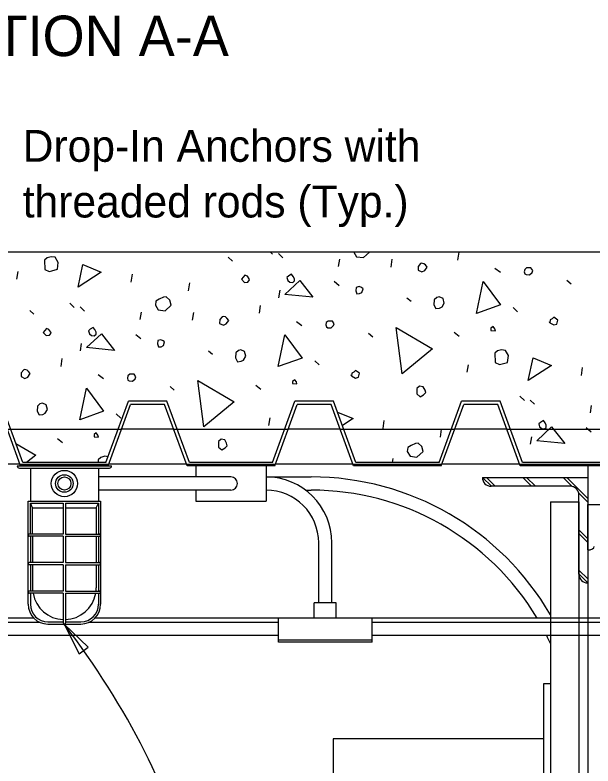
# Model space of a CAD drawing. Extents: x 112544 to 112597.1, y 111084 to 111107.1.
# Drawn here: x 112559.102 to 112561.845, y 111092 to 111095.563 of the extents above; entities that cross this region are included whole.
import ezdxf

# ---------------------------------------------------------------- set-up
doc = ezdxf.new("R2010")
doc.units = 0
for name, color, linetype in [('Dimension', 7, 'Continuous'), ('Lighting', 7, 'Continuous'), ('Lighting_h', 7, 'Continuous'), ('Miscellaneous', 7, 'Continuous'), ('SteelGirder', 7, 'Continuous'), ('SteelGirder_h', 7, 'Continuous'), ('SupstrConc', 7, 'Continuous'), ('TextStructures', 7, 'Continuous')]:
    doc.layers.add(name, color=color, linetype=linetype)

msp = doc.modelspace()

# ---------------------------------------------------------------- linework, layer by layer
at = {"layer": 'Dimension'}
msp.add_lwpolyline([(112559.3342, 111092.6735), (112559.4058, 111092.5322), (112559.4483, 111092.5637)], close=True, dxfattribs=at)
msp.add_ellipse((112558.9681, 111092.2177), major_axis=(-0.8636, 1.2185), ratio=0.378675, start_param=2.874358, end_param=4.819841, dxfattribs=at)
at = {"layer": 'Lighting'}
for p, q in [((112559.112, 111093.4235), (112559.5599, 111093.4235)), ((112559.1224, 111093.4131), (112559.5495, 111093.4131)), ((112559.1745, 111093.4235), (112559.4974, 111093.4235)), ((112559.1745, 111093.4131), (112559.1745, 111093.2568)), ((112559.4974, 111093.4131), (112559.4974, 111093.2568)), ((112560.2931, 111093.4235), (112559.9598, 111093.4235)), ((112559.9598, 111093.4235), (112559.9598, 111093.3714)), ((112560.2931, 111093.4235), (112560.2931, 111093.2568)), ((112560.1264, 111093.3714), (112559.4974, 111093.3714)), ((112560.2931, 111093.3714), (112560.5076, 111093.3714)), ((112560.1264, 111093.3089), (112559.4974, 111093.3089)), ((112559.9598, 111093.3089), (112559.9598, 111093.2568)), ((112560.4806, 111093.3089), (112560.5076, 111093.3089)), ((112559.1641, 111092.7672), (112559.1641, 111093.2568)), ((112559.1641, 111093.2568), (112559.1745, 111093.2568)), ((112559.1745, 111093.2568), (112559.4974, 111093.2568)), ((112559.1745, 111093.1006), (112559.1745, 111093.2464)), ((112559.1745, 111093.2464), (112559.3308, 111093.2464)), ((112559.1849, 111093.2256), (112559.1745, 111093.2464)), ((112559.3308, 111093.2464), (112559.3308, 111093.1006)), ((112559.3412, 111093.2464), (112559.4974, 111093.2464)), ((112559.3412, 111093.2464), (112559.3412, 111093.1006)), ((112559.487, 111093.2256), (112559.4974, 111093.2464)), ((112559.4974, 111093.2568), (112559.5078, 111093.2568)), ((112559.4974, 111093.2464), (112559.4974, 111093.1006)), ((112559.5078, 111093.2568), (112559.5078, 111092.7672)), ((112559.9598, 111093.2568), (112560.2931, 111093.2568)), ((112561.6431, 111093.254), (112561.6431, 111092.3909)), ((112561.6431, 111093.254), (112561.7785, 111093.254)), ((112561.7785, 111093.254), (112561.7785, 111088.8165)), ((112559.1849, 111093.2256), (112559.3308, 111093.2256)), ((112559.3412, 111093.2256), (112559.487, 111093.2256)), ((112559.3308, 111093.1006), (112559.1693, 111093.1006)), ((112559.3308, 111093.0902), (112559.1693, 111093.0902)), ((112559.1745, 111093.0902), (112559.1745, 111092.9652)), ((112559.3308, 111093.0902), (112559.3308, 111092.9652)), ((112559.3412, 111093.1006), (112559.5026, 111093.1006)), ((112559.3412, 111093.0902), (112559.5026, 111093.0902)), ((112559.3412, 111093.0902), (112559.3412, 111092.9652)), ((112559.4974, 111093.0902), (112559.4974, 111092.9652)), ((112560.5431, 111092.774), (112560.5431, 111093.0589)), ((112560.6056, 111092.774), (112560.6056, 111093.0589)), ((112559.3308, 111092.9652), (112559.1693, 111092.9652)), ((112559.3412, 111092.9652), (112559.5026, 111092.9652)), ((112559.3308, 111092.9548), (112559.1693, 111092.9548)), ((112559.1745, 111092.9548), (112559.1745, 111092.8298)), ((112559.3308, 111092.9548), (112559.3308, 111092.8298)), ((112559.3412, 111092.9548), (112559.5026, 111092.9548)), ((112559.3412, 111092.9548), (112559.3412, 111092.8298)), ((112559.4974, 111092.9548), (112559.4974, 111092.8298)), ((112559.3308, 111092.8298), (112559.1693, 111092.8298)), ((112559.3308, 111092.8194), (112559.1693, 111092.8194)), ((112559.1745, 111092.8194), (112559.1745, 111092.7672)), ((112559.3308, 111092.8194), (112559.3308, 111092.6787)), ((112559.3412, 111092.8298), (112559.5026, 111092.8298)), ((112559.3412, 111092.8194), (112559.5026, 111092.8194)), ((112559.3412, 111092.8194), (112559.3412, 111092.6787)), ((112559.4974, 111092.8194), (112559.4974, 111092.7672)), ((112560.6264, 111092.774), (112560.5223, 111092.774)), ((112560.5223, 111092.7018), (112560.5223, 111092.774)), ((112560.6264, 111092.7018), (112560.6264, 111092.774)), ((112559.1907, 111092.7018), (112558.4355, 111092.7018)), ((112559.2211, 111092.681), (112558.4355, 111092.681)), ((112559.2578, 111092.6839), (112559.3308, 111092.6839)), ((112559.3412, 111092.6839), (112559.4141, 111092.6839)), ((112560.3522, 111092.681), (112559.4509, 111092.681)), ((112560.3805, 111092.7018), (112559.4813, 111092.7018)), ((112560.3522, 111092.5877), (112560.3522, 111092.7018)), ((112561.6431, 111092.7018), (112560.3522, 111092.7018)), ((112560.7964, 111092.5877), (112560.7964, 111092.7018)), ((112561.6431, 111092.681), (112560.7964, 111092.681)), ((112559.2578, 111092.6735), (112559.4141, 111092.6735)), ((112560.3522, 111092.6185), (112558.4355, 111092.6185)), ((112561.6431, 111092.6185), (112560.7964, 111092.6185)), ((112560.7964, 111092.5977), (112560.3522, 111092.5977)), ((112560.7964, 111092.5877), (112560.3522, 111092.5877))]:
    msp.add_line(p, q, dxfattribs=at)
msp.add_lwpolyline([(112561.6119, 111089.4034), (112561.6119, 111092.1284), (112560.6119, 111092.1284), (112560.6119, 111089.4034), (112561.5494, 111089.4034)], dxfattribs=at)
for radius in [0.0625, 0.0417, 0.0312]:
    msp.add_circle((112559.336, 111093.3402), radius, dxfattribs=at)
for centre, radius, start, end in [((112559.1224, 111093.4235), 0.0104, 180, 270), ((112559.5495, 111093.4235), 0.0104, 270, 0), ((112560.1264, 111093.3402), 0.0312, 270, 90), ((112560.2931, 111093.0589), 0.3125, 0, 90), ((112560.5076, 111092.0589), 1.3125, 30.1068, 90), ((112560.2931, 111093.0589), 0.25, 0, 90), ((112560.5076, 111092.0589), 1.25, 30.9531, 90), ((112559.1693, 111093.0954), 0.0052, 89.9999, 270), ((112559.5026, 111093.0954), 0.0052, 270, 90.0001), ((112559.1693, 111092.96), 0.0052, 89.9999, 270), ((112559.5026, 111092.96), 0.0052, 270, 90.0001), ((112559.1693, 111092.8246), 0.0052, 89.9999, 270), ((112559.5026, 111092.8246), 0.0052, 270, 90.0001), ((112559.2578, 111092.7672), 0.0937, 180, 270), ((112559.2578, 111092.7672), 0.0833, 180, 270), ((112559.4141, 111092.7672), 0.0833, 270, 0), ((112559.4141, 111092.7672), 0.0937, 270, 0), ((112559.336, 111092.6787), 0.0052, 179.9665, 0), ((112560.5076, 111092.0589), 1.25, 24.7221, 26.596)]:
    msp.add_arc(centre, radius, start, end, dxfattribs=at)
at = {"layer": 'Lighting_h'}
for p, q in [((112562.2368, 111092.7018), (112561.6431, 111092.7018)), ((112562.2368, 111092.681), (112561.6431, 111092.681)), ((112562.2368, 111092.6185), (112561.6431, 111092.6185))]:
    msp.add_line(p, q, dxfattribs=at)
at = {"layer": 'Miscellaneous'}
for p, q in [((112560.3127, 111094.4392), (112560.324, 111094.4283)), ((112560.3518, 111094.4306), (112560.3728, 111094.4103)), ((112561.2038, 111094.4), (112561.2092, 111094.4377)), ((112560.1132, 111094.4132), (112560.1335, 111094.3954)), ((112560.6373, 111094.3699), (112560.6434, 111094.4052)), ((112560.8866, 111094.3668), (112560.892, 111094.4045)), ((112561.3797, 111094.3618), (112561.4055, 111094.3428)), ((112559.1107, 111094.3102), (112559.1168, 111094.3455)), ((112559.6531, 111094.2951), (112559.6585, 111094.3328)), ((112559.9255, 111094.2542), (112559.9309, 111094.2919)), ((112560.6172, 111094.2998), (112560.6406, 111094.2802)), ((112561.7208, 111094.3056), (112561.7411, 111094.2878)), ((112560.3535, 111094.2214), (112560.3596, 111094.2567)), ((112560.9618, 111094.2213), (112560.9815, 111094.2059)), ((112559.3612, 111094.1962), (112559.3822, 111094.1759)), ((112559.4101, 111094.1782), (112559.431, 111094.158)), ((112560.262, 111094.1477), (112560.2674, 111094.1854)), ((112561.4659, 111094.1752), (112561.4869, 111094.155)), ((112559.1714, 111094.1609), (112559.1917, 111094.143)), ((112559.6955, 111094.1175), (112559.7016, 111094.1528)), ((112559.9448, 111094.1145), (112559.9502, 111094.1521)), ((112560.4379, 111094.1094), (112560.4637, 111094.0904)), ((112559.6755, 111094.0475), (112559.6988, 111094.0278)), ((112560.779, 111094.0533), (112560.7994, 111094.0354)), ((112561.1865, 111094.0589), (112561.2098, 111094.0393)), ((112559.4118, 111093.969), (112559.4178, 111094.0043)), ((112560.02, 111093.969), (112560.0397, 111093.9535)), ((112559.3202, 111093.8953), (112559.3256, 111093.933)), ((112560.5241, 111093.9229), (112560.5451, 111093.9026)), ((112561.2479, 111093.8683), (112561.254, 111093.9036)), ((112561.7903, 111093.8532), (112561.7957, 111093.8909)), ((112559.4961, 111093.8571), (112559.5219, 111093.8381)), ((112559.8373, 111093.8009), (112559.8576, 111093.7831)), ((112560.2447, 111093.8066), (112560.2681, 111093.787)), ((112561.4984, 111093.7543), (112561.5194, 111093.734)), ((112559.1277, 111093.4235), (112559.0215, 111093.7153)), ((112559.1386, 111093.4391), (112559.0324, 111093.7309)), ((112559.5334, 111093.4391), (112559.6396, 111093.7309)), ((112559.5443, 111093.4235), (112559.6505, 111093.7153)), ((112559.8229, 111093.7309), (112559.6396, 111093.7309)), ((112559.8119, 111093.7153), (112559.6505, 111093.7153)), ((112559.9181, 111093.4235), (112559.8119, 111093.7153)), ((112559.9291, 111093.4391), (112559.8229, 111093.7309)), ((112560.3238, 111093.4391), (112560.43, 111093.7309)), ((112560.3347, 111093.4235), (112560.4409, 111093.7153)), ((112560.6133, 111093.7309), (112560.43, 111093.7309)), ((112560.6024, 111093.7153), (112560.4409, 111093.7153)), ((112560.7086, 111093.4235), (112560.6024, 111093.7153)), ((112560.7195, 111093.4391), (112560.6133, 111093.7309)), ((112561.1142, 111093.4391), (112561.2204, 111093.7309)), ((112561.1252, 111093.4235), (112561.2314, 111093.7153)), ((112561.4037, 111093.7309), (112561.2204, 111093.7309)), ((112561.3928, 111093.7153), (112561.2314, 111093.7153)), ((112561.499, 111093.4235), (112561.3928, 111093.7153)), ((112561.5099, 111093.4391), (112561.4037, 111093.7309)), ((112561.5473, 111093.7363), (112561.5682, 111093.7161)), ((112561.8327, 111093.6756), (112561.8388, 111093.7109)), ((112559.5823, 111093.6705), (112559.6033, 111093.6503)), ((112560.3061, 111093.616), (112560.3122, 111093.6513)), ((112560.8485, 111093.6009), (112560.8539, 111093.6385)), ((112561.8126, 111093.6056), (112561.836, 111093.5859)), ((112561.1209, 111093.56), (112561.1263, 111093.5976)), ((112559.3029, 111093.5542), (112559.3263, 111093.5346)), ((112561.549, 111093.5271), (112561.555, 111093.5624)), ((112559.5334, 111093.4391), (112559.1386, 111093.4391)), ((112560.3238, 111093.4391), (112559.9291, 111093.4391)), ((112561.1142, 111093.4391), (112560.7195, 111093.4391)), ((112560.8936, 111093.4391), (112560.897, 111093.4586)), ((112561.9047, 111093.4391), (112561.5099, 111093.4391)), ((112559.5443, 111093.4235), (112559.1277, 111093.4235)), ((112560.3347, 111093.4235), (112559.9181, 111093.4235)), ((112561.1252, 111093.4235), (112560.7086, 111093.4235)), ((112561.9156, 111093.4235), (112561.499, 111093.4235)), ((112561.363, 111093.3269), (112561.3214, 111093.3686)), ((112561.3807, 111093.3269), (112561.339, 111093.3686)), ((112561.554, 111093.3269), (112561.5123, 111093.3686)), ((112561.5716, 111093.3269), (112561.53, 111093.3686)), ((112561.7473, 111093.3245), (112561.7032, 111093.3686)), ((112561.8201, 111093.2693), (112561.7209, 111093.3686)), ((112561.8201, 111093.2517), (112561.7758, 111093.296)), ((112559.1849, 111093.1006), (112559.1849, 111093.2256)), ((112559.487, 111093.2256), (112559.487, 111093.1006)), ((112561.8201, 111093.0784), (112561.7785, 111093.1201)), ((112559.1849, 111093.0902), (112559.1849, 111092.9652)), ((112559.487, 111093.0902), (112559.487, 111092.9652)), ((112561.8201, 111093.0607), (112561.7785, 111093.1024)), ((112559.1849, 111092.9548), (112559.1849, 111092.8453)), ((112559.487, 111092.9548), (112559.487, 111092.8453)), ((112561.8201, 111092.8875), (112561.7785, 111092.9292)), ((112561.8201, 111092.8698), (112561.7785, 111092.9115))]:
    msp.add_line(p, q, dxfattribs=at)
for points in [[(112560.7095, 111094.4384), (112560.7232, 111094.4162), (112560.7554, 111094.4119), (112560.7847, 111094.4379), (112560.7843, 111094.4392)], [(112560.7096, 111094.4392), (112560.7095, 111094.4384)], [(112559.242, 111094.3998), (112559.2433, 111094.3561), (112559.2641, 111094.3462), (112559.2762, 111094.3494), (112559.3028, 111094.3565), (112559.3071, 111094.3887), (112559.2927, 111094.4134), (112559.2739, 111094.4161), (112559.2545, 111094.4109), (112559.242, 111094.3998)], [(112559.4006, 111094.2715), (112559.4237, 111094.3786), (112559.511, 111094.3425), (112559.4006, 111094.2715)], [(112561.0151, 111094.3702), (112561.0148, 111094.352), (112561.0325, 111094.3438), (112561.0463, 111094.3501), (112561.0576, 111094.366), (112561.0495, 111094.3768), (112561.0428, 111094.3828), (112561.0318, 111094.385), (112561.027, 111094.3837), (112561.0151, 111094.3702)], [(112561.5214, 111094.335), (112561.5275, 111094.3315), (112561.5433, 111094.3306), (112561.5559, 111094.3417), (112561.5588, 111094.3502), (112561.5501, 111094.3634), (112561.5294, 111094.3631), (112561.5211, 111094.3556), (112561.5188, 111094.3447), (112561.5214, 111094.335)], [(112560.1774, 111094.3088), (112560.1916, 111094.2945), (112560.2067, 111094.2959), (112560.2145, 111094.3058), (112560.2132, 111094.3106), (112560.2045, 111094.3238), (112560.1929, 111094.3285), (112560.1851, 111094.3186), (112560.1774, 111094.3088)], [(112560.3964, 111094.3028), (112560.4063, 111094.2951), (112560.4196, 111094.2935), (112560.428, 111094.3009), (112560.4278, 111094.3112), (112560.4222, 111094.3226), (112560.4141, 111094.3334), (112560.4009, 111094.3247), (112560.3926, 111094.3173), (112560.3964, 111094.3028)], [(112560.383, 111094.237), (112560.4534, 111094.3025), (112560.516, 111094.2235), (112560.383, 111094.237)], [(112561.2923, 111094.1468), (112561.3244, 111094.2978), (112561.4057, 111094.1875), (112561.2923, 111094.1468)], [(112560.7199, 111094.2548), (112560.7237, 111094.2404), (112560.7365, 111094.2412), (112560.7479, 111094.2468), (112560.7537, 111094.2639), (112560.7469, 111094.2699), (112560.7353, 111094.2745), (112560.7208, 111094.2706), (112560.7199, 111094.2548)], [(112559.7677, 111094.1861), (112559.7814, 111094.1639), (112559.8136, 111094.1596), (112559.8429, 111094.1855), (112559.8365, 111094.2097), (112559.8192, 111094.2257), (112559.8065, 111094.2249), (112559.786, 111094.2143), (112559.7704, 111094.2049), (112559.7677, 111094.1861)], [(112561.0911, 111094.212), (112561.0897, 111094.1883), (112561.0997, 111094.1703), (112561.1172, 111094.1724), (112561.1287, 111094.178), (112561.1393, 111094.1964), (112561.1335, 111094.2181), (112561.1157, 111094.2263), (112561.1037, 111094.2231), (112561.0911, 111094.212)], [(112560.0733, 111094.1178), (112560.073, 111094.0996), (112560.0907, 111094.0914), (112560.1046, 111094.0977), (112560.1158, 111094.1137), (112560.1077, 111094.1245), (112560.101, 111094.1304), (112560.09, 111094.1327), (112560.0852, 111094.1314), (112560.0733, 111094.1178)], [(112560.5796, 111094.0827), (112560.5858, 111094.0792), (112560.6016, 111094.0782), (112560.6141, 111094.0893), (112560.617, 111094.0979), (112560.6083, 111094.1111), (112560.5877, 111094.1107), (112560.5793, 111094.1033), (112560.5771, 111094.0923), (112560.5796, 111094.0827)], [(112561.6405, 111094.103), (112561.6589, 111094.0924), (112561.6734, 111094.0962), (112561.6785, 111094.1157), (112561.6595, 111094.1287), (112561.6512, 111094.1213), (112561.6421, 111094.1163), (112561.6405, 111094.103), (112561.6393, 111094.1078)], [(112559.2356, 111094.0564), (112559.2498, 111094.0421), (112559.265, 111094.0436), (112559.2727, 111094.0534), (112559.2714, 111094.0583), (112559.2627, 111094.0714), (112559.2511, 111094.0761), (112559.2434, 111094.0663), (112559.2356, 111094.0564)], [(112559.4547, 111094.0504), (112559.4645, 111094.0427), (112559.4779, 111094.0411), (112559.4862, 111094.0485), (112559.4861, 111094.0588), (112559.4804, 111094.0703), (112559.4723, 111094.081), (112559.4591, 111094.0723), (112559.4508, 111094.0649), (112559.4547, 111094.0504)], [(112560.9394, 111093.8607), (112560.9114, 111094.081), (112561.0835, 111093.9796), (112560.9394, 111093.8607)], [(112561.3604, 111094.0667), (112561.3816, 111094.0646), (112561.3791, 111094.0743), (112561.371, 111094.0851), (112561.3602, 111094.077), (112561.3604, 111094.0667)], [(112559.4412, 111093.9847), (112559.5117, 111094.0502), (112559.5742, 111093.9712), (112559.4412, 111093.9847)], [(112560.3506, 111093.8945), (112560.3826, 111094.0454), (112560.4639, 111093.9352), (112560.3506, 111093.8945)], [(112559.7781, 111094.0025), (112559.782, 111093.988), (112559.7947, 111093.9888), (112559.8061, 111093.9945), (112559.8119, 111094.0116), (112559.8051, 111094.0175), (112559.7935, 111094.0222), (112559.779, 111094.0183), (112559.7781, 111094.0025)], [(112560.1493, 111093.9596), (112560.1479, 111093.9359), (112560.1579, 111093.9179), (112560.1755, 111093.92), (112560.1869, 111093.9257), (112560.1975, 111093.9441), (112560.1917, 111093.9658), (112560.174, 111093.974), (112560.1619, 111093.9707), (112560.1493, 111093.9596)], [(112561.3792, 111093.9579), (112561.3805, 111093.9142), (112561.4013, 111093.9043), (112561.4134, 111093.9075), (112561.44, 111093.9146), (112561.4443, 111093.9468), (112561.4299, 111093.9715), (112561.4111, 111093.9742), (112561.3917, 111093.969), (112561.3792, 111093.9579)], [(112561.5378, 111093.8296), (112561.5609, 111093.9367), (112561.6482, 111093.9005), (112561.5378, 111093.8296)], [(112559.1315, 111093.8655), (112559.1312, 111093.8473), (112559.1489, 111093.8391), (112559.1628, 111093.8454), (112559.174, 111093.8613), (112559.166, 111093.8721), (112559.1592, 111093.8781), (112559.1482, 111093.8803), (112559.1434, 111093.879), (112559.1315, 111093.8655)], [(112559.6379, 111093.8303), (112559.644, 111093.8268), (112559.6598, 111093.8259), (112559.6723, 111093.837), (112559.6752, 111093.8455), (112559.6665, 111093.8587), (112559.6459, 111093.8584), (112559.6375, 111093.851), (112559.6353, 111093.84), (112559.6379, 111093.8303)], [(112560.6988, 111093.8506), (112560.7171, 111093.84), (112560.7316, 111093.8439), (112560.7368, 111093.8634), (112560.7177, 111093.8764), (112560.7094, 111093.869), (112560.7004, 111093.864), (112560.6988, 111093.8506), (112560.6975, 111093.8554)], [(112559.9976, 111093.6084), (112559.9696, 111093.8286), (112560.1417, 111093.7272), (112559.9976, 111093.6084)], [(112560.4186, 111093.8144), (112560.4399, 111093.8123), (112560.4373, 111093.822), (112560.4292, 111093.8327), (112560.4184, 111093.8247), (112560.4186, 111093.8144)], [(112559.4088, 111093.6421), (112559.4408, 111093.7931), (112559.5221, 111093.6828), (112559.4088, 111093.6421)], [(112561.0092, 111093.7837), (112561.0089, 111093.7655), (112561.0255, 111093.7518), (112561.0411, 111093.7612), (112561.0512, 111093.7716), (112561.048, 111093.7837), (112561.0386, 111093.7993), (112561.0222, 111093.8027), (112561.0096, 111093.7916), (112561.0092, 111093.7837)], [(112559.2076, 111093.7073), (112559.2061, 111093.6836), (112559.2161, 111093.6656), (112559.2337, 111093.6677), (112559.2451, 111093.6733), (112559.2557, 111093.6917), (112559.2499, 111093.7134), (112559.2322, 111093.7216), (112559.2201, 111093.7184), (112559.2076, 111093.7073)], [(112560.6322, 111093.6789), (112560.7064, 111093.6482), (112560.6554, 111093.6154)], [(112561.5919, 111093.6085), (112561.6017, 111093.6008), (112561.6151, 111093.5992), (112561.6234, 111093.6066), (112561.6233, 111093.6169), (112561.6176, 111093.6283), (112561.6095, 111093.6391), (112561.5963, 111093.6304), (112561.588, 111093.623), (112561.5919, 111093.6085)], [(112561.5784, 111093.5428), (112561.6489, 111093.6083), (112561.7114, 111093.5293), (112561.5784, 111093.5428)], [(112559.4768, 111093.562), (112559.4981, 111093.5599), (112559.4955, 111093.5696), (112559.4874, 111093.5804), (112559.4767, 111093.5723), (112559.4768, 111093.562)], [(112560.0674, 111093.5313), (112560.0671, 111093.5131), (112560.0837, 111093.4995), (112560.0993, 111093.5088), (112560.1094, 111093.5193), (112560.1062, 111093.5314), (112560.0968, 111093.547), (112560.0804, 111093.5503), (112560.0679, 111093.5392), (112560.0674, 111093.5313)], [(112560.9631, 111093.4918), (112560.9769, 111093.4696), (112561.0091, 111093.4653), (112561.0383, 111093.4913), (112561.0319, 111093.5154), (112561.0146, 111093.5315), (112561.0019, 111093.5307), (112560.9815, 111093.52), (112560.9659, 111093.5107), (112560.9631, 111093.4918)], [(112559.1053, 111093.5306), (112559.1999, 111093.4749), (112559.1566, 111093.4391)], [(112559.5436, 111093.4672), (112559.5275, 111093.4695), (112559.5082, 111093.4643), (112559.4956, 111093.4532)], [(112559.4956, 111093.4532), (112559.4961, 111093.4391)]]:
    msp.add_lwpolyline(points, dxfattribs=at)
for start, end in [(180, 185.9203), (189.9053, 268.0265), (271.9735, 350.0947), (354.0797, 0)]:
    msp.add_arc((112559.336, 111092.8453), 0.151, start, end, dxfattribs=at)
at = {"layer": 'SteelGirder'}
for p, q in [((112559.8547, 111093.5979), (112559.6078, 111093.5979)), ((112560.6451, 111093.5979), (112560.3982, 111093.5979)), ((112561.4356, 111093.5979), (112561.1886, 111093.5979)), ((112559.1249, 111093.4312), (112558.7566, 111093.4312)), ((112559.9154, 111093.4312), (112559.5471, 111093.4312)), ((112560.7058, 111093.4312), (112560.3375, 111093.4312)), ((112561.4962, 111093.4312), (112561.1279, 111093.4312)), ((112561.8201, 111093.4312), (112561.8201, 111093.3686)), ((112561.3201, 111093.3686), (112561.8201, 111093.3686)), ((112561.8201, 111093.3686), (112561.8201, 111092.8686)), ((112561.7368, 111093.3269), (112561.3618, 111093.3269)), ((112561.7785, 111092.9103), (112561.7785, 111093.2853)), ((112561.8201, 111093.025), (112561.8201, 111093.2407)), ((112561.8201, 111093.2407), (112562.2368, 111093.2407)), ((112561.8201, 111092.8686), (112561.8201, 111087.9832))]:
    msp.add_line(p, q, dxfattribs=at)
msp.add_lwpolyline([(112561.6119, 111092.3909), (112561.6431, 111092.3909), (112561.6431, 111089.1409), (112561.6119, 111089.1409)], close=True, dxfattribs=at)
for centre, start, end in [((112561.3618, 111093.3686), 180, 270), ((112561.7368, 111093.2853), 0, 90), ((112561.8201, 111092.9103), 180, 270)]:
    msp.add_arc(centre, 0.0417, start, end, dxfattribs=at)
msp.add_ellipse((112561.8201, 111093.0412), major_axis=(0.0312, 0), ratio=0.5176, start_param=4.712389, end_param=6.283185, dxfattribs=at)
at = {"layer": 'SteelGirder_h'}
for p, q in [((112559.0642, 111093.5979), (112559.6078, 111093.5979)), ((112559.8547, 111093.5979), (112560.3982, 111093.5979)), ((112560.6451, 111093.5979), (112561.1886, 111093.5979)), ((112561.4355, 111093.5979), (112561.9791, 111093.5979)), ((112559.1249, 111093.4312), (112559.5471, 111093.4312)), ((112559.9154, 111093.4312), (112560.3375, 111093.4312)), ((112560.7058, 111093.4312), (112561.1279, 111093.4312)), ((112561.4962, 111093.4312), (112561.9184, 111093.4312))]:
    msp.add_line(p, q, dxfattribs=at)
at = {"layer": 'SupstrConc'}
msp.add_line((112557.7434, 111094.4392), (112564.7526, 111094.4392), dxfattribs=at)

# ---------------------------------------------------------------- texts
at = {"layer": 'Dimension'}
for s, p in [('Drop-In Anchors with', (112559.1381, 111094.8662)), ('threaded rods (Typ.)', (112559.1381, 111094.6022))]:
    msp.add_text(s, height=0.1512, dxfattribs=at).set_placement(p)
at = {"layer": 'TextStructures'}
msp.add_text('SECTION A-A', height=0.192, dxfattribs=at).set_placement((112558.4762, 111095.3677))

doc.saveas('drawing.dxf')
